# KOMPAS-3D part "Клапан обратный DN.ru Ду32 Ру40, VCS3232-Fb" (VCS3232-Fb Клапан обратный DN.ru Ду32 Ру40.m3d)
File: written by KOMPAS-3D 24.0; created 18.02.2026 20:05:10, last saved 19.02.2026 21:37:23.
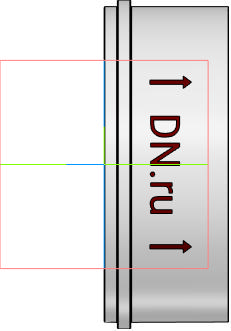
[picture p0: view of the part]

Document properties: Автор: R2D2; Полное имя файла: D:\Работа\Клапаны обратные\VCS3232-Fb Клапан обратный DN.ru Ду15-100\DN32\VCS3232-Fb Клапан обратный DN.ru Ду32 Ру40.m3d

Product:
- Body: Тело 1  | qty 1
    Масса: 0.328859
- Body: Тело 2  | qty 1
    Масса: 0.117367
- Part/product: Клапан обратный DN.ru Ду32 Ру40  | designation VCS3232-Fb
    Масса: 0.5
    Раздел спецификации: Прочие изделия
    Примечание: D100-03708
    additional columns: 1; D100-03708

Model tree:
1. Операция без истории:1
2. Операция без истории:2

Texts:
  Точка начала. Х
  Точка начала. Y
  Точка начала. Z
  VCS3232-Fb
